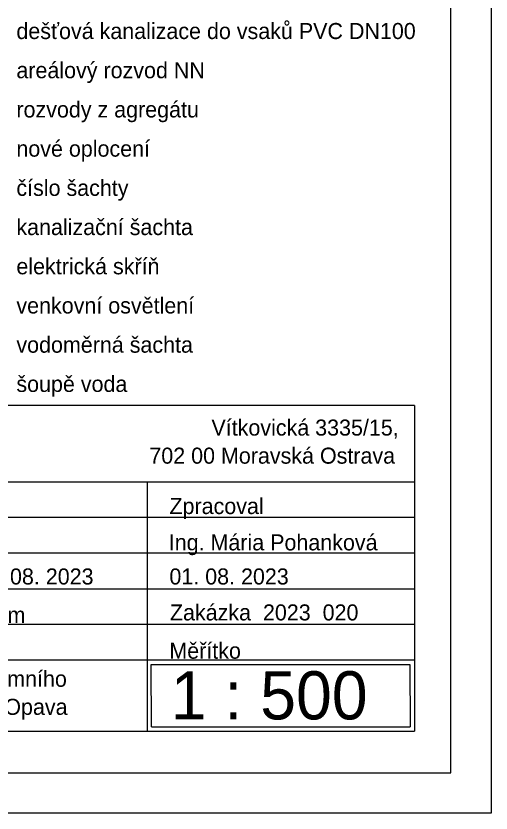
# Model space of a CAD drawing. Extents: x -497549 to -497344, y -1086547 to -1086398.
# Drawn here: x -497374.04 to -497344.44, y -1086546.87 to -1086497.19 of the extents above; entities that cross this region are included whole.
import ezdxf

# ---------------------------------------------------------------- set-up
doc = ezdxf.new("R2010")
doc.units = 0
doc.layers.add('Vrstva 63', color=7, linetype='Continuous')

msp = doc.modelspace()

# ---------------------------------------------------------------- linework, layer by layer
at = {"layer": 'Vrstva 63'}
for p, q in [((-497349.206, -1086521.477), (-497349.206, -1086541.772)), ((-497399.206, -1086526.218), (-497349.206, -1086526.218)), ((-497365.872, -1086526.218), (-497365.872, -1086541.772)), ((-497399.206, -1086528.438), (-497349.206, -1086528.438)), ((-497399.206, -1086530.66), (-497349.206, -1086530.66)), ((-497399.206, -1086532.884), (-497349.206, -1086532.884)), ((-497399.206, -1086535.104), (-497349.206, -1086535.104)), ((-497399.206, -1086537.328), (-497349.206, -1086537.328)), ((-497365.606, -1086537.604), (-497349.494, -1086537.604)), ((-497365.594, -1086541.496), (-497365.606, -1086537.604)), ((-497349.494, -1086537.604), (-497349.482, -1086541.496)), ((-497365.594, -1086541.496), (-497349.482, -1086541.496)), ((-497399.206, -1086541.772), (-497349.206, -1086541.772))]:
    msp.add_line(p, q, dxfattribs=at)
msp.add_lwpolyline([(-497549.436, -1086398.366), (-497344.436, -1086398.366), (-497344.436, -1086546.866), (-497549.436, -1086546.866)], close=True, dxfattribs=at)
for points in [[(-497546.936, -1086400.866), (-497546.936, -1086544.366), (-497346.936, -1086544.366), (-497346.936, -1086400.866)], [(-497546.936, -1086400.866), (-497546.936, -1086544.366), (-497346.936, -1086544.366), (-497346.936, -1086400.866)], [(-497349.206, -1086521.477), (-497399.206, -1086521.477), (-497399.206, -1086541.772)]]:
    msp.add_lwpolyline(points, dxfattribs=at)

# ---------------------------------------------------------------- texts
for s, height, p in [('dešťová kanalizace do vsaků PVC DN100', 1, (-497374.012, -1086498.634)), ('areálový rozvod NN', 1, (-497374.012, -1086501.077)), ('rozvody z agregátu', 1, (-497374.012, -1086503.521)), ('nové oplocení', 1, (-497374.012, -1086505.964)), ('číslo šachty', 1, (-497374.012, -1086508.407)), ('kanalizační šachta', 1, (-497374.012, -1086510.851)), ('elektrická skříň', 1, (-497374.012, -1086513.294)), ('venkovní osvětlení', 1, (-497374.012, -1086515.737)), ('vodoměrná šachta', 1, (-497374.012, -1086518.18)), ('šoupě voda', 1, (-497374.012, -1086520.624)), ('Vítkovická 3335/15, ', 1, (-497361.859, -1086523.345)), ('702 00 Moravská Ostrava', 1, (-497365.726, -1086525.095)), ('Zpracoval', 1, (-497364.476, -1086528.235)), ('Ing. Mária Pohanková', 1, (-497364.518, -1086530.499)), ('27.06. - 01. 08. 2023', 1, (-497381.547, -1086532.623)), ('01. 08. 2023', 1, (-497364.477, -1086532.623)), ('Výšk. systém', 1, (-497381.327, -1086535.021)), ('Zakázka  2023_020', 1, (-497364.446, -1086534.863)), ('Měřítko', 1, (-497364.481, -1086537.249)), ('Zaměření skutečného provedení zimního', 1, (-497395.174, -1086538.997)), ('1 : 500', 3, (-497364.395, -1086541.03)), ('stadionu - náhradní ledové plochy Opava', 1, (-497395.209, -1086540.747))]:
    msp.add_text(s, height=height, dxfattribs=at).set_placement(p)

doc.saveas('drawing.dxf')
